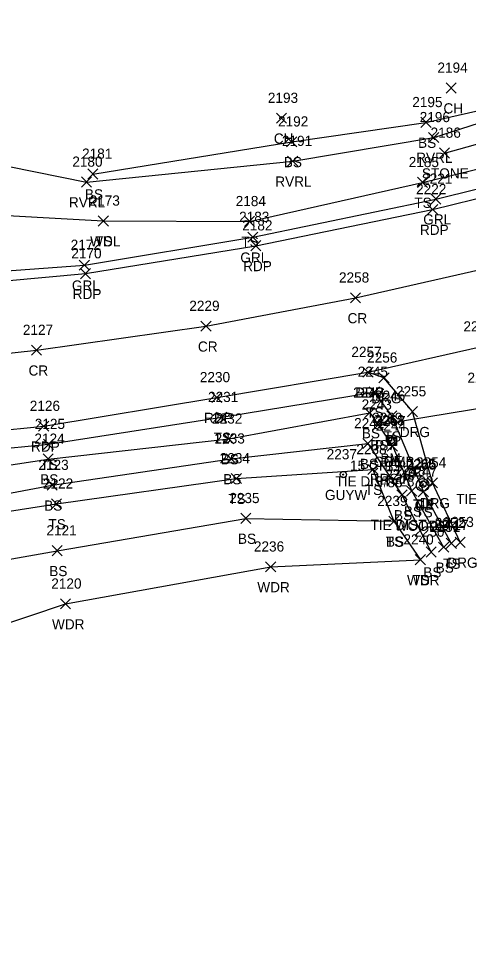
# Model space of a CAD drawing. Extents: x 1699408 to 1700423, y 840176 to 841410.
# Drawn here: x 1699767.4 to 1699855.8, y 840198.9 to 840382.8 of the extents above; entities that cross this region are included whole.
import ezdxf

# ---------------------------------------------------------------- set-up
doc = ezdxf.new("R2010")
doc.units = 0
for name, color, linetype in [('C_A', 7, 'Continuous'), ('C_C', 7, 'Continuous'), ('C_I', 7, 'Continuous'), ('CBP', 7, 'Continuous'), ('CPBM', 7, 'Continuous'), ('D_A', 7, 'Continuous'), ('D_I', 7, 'Continuous'), ('D_TIC', 7, 'Continuous'), ('DCP', 7, 'Continuous'), ('L_A', 7, 'Continuous'), ('L_C', 7, 'Continuous'), ('L_I', 7, 'Continuous'), ('L_TIC', 7, 'Continuous'), ('LASF', 7, 'Continuous'), ('LAWA', 7, 'Continuous'), ('LAWE', 7, 'Continuous'), ('LELB', 7, 'Continuous'), ('P_A', 7, 'Continuous'), ('P_I', 7, 'Continuous'), ('P_TIC', 7, 'Continuous'), ('PET', 7, 'Continuous'), ('PRC', 7, 'Continuous'), ('R_A', 7, 'Continuous'), ('R_C', 7, 'Continuous'), ('R_I', 7, 'Continuous'), ('R_TIC', 7, 'Continuous'), ('RDG', 7, 'Continuous'), ('RGP', 7, 'Continuous'), ('RGR', 7, 'Continuous'), ('U_A', 7, 'Continuous'), ('U_C', 7, 'Continuous'), ('U_I', 7, 'Continuous'), ('UP', 7, 'Continuous'), ('UPGW', 7, 'Continuous')]:
    doc.layers.add(name, color=color, linetype=linetype)

msp = doc.modelspace()

# ---------------------------------------------------------------- linework, layer by layer
at = {"layer": 'CBP'}
for centre, radius in [((1699840.65, 840299.96), 0.625), ((1699840.65, 840299.96), 0.0833), ((1699846.89, 840291.41), 0.625), ((1699846.89, 840291.41), 0.0833)]:
    msp.add_circle(centre, radius, dxfattribs=at)
at = {"layer": 'CPBM'}
for p, q in [((1699839.71, 840299.93), (1699839.71, 840300.94)), ((1699839.71, 840300.94), (1699840.71, 840300.94)), ((1699840.71, 840299.93), (1699839.71, 840299.93)), ((1699840.22, 840300.44), (1699840.22, 840300.44)), ((1699840.22, 840300.44), (1699840.22, 840300.44)), ((1699840.71, 840300.94), (1699840.71, 840299.93))]:
    msp.add_line(p, q, dxfattribs=at)
at = {"layer": 'D_TIC'}
for points in [[(1699837.09, 840302.05), (1699839.09, 840304.05)], [(1699839.09, 840302.05), (1699837.09, 840304.05)]]:
    msp.add_lwpolyline(points, dxfattribs=at)
at = {"layer": 'DCP'}
msp.add_lwpolyline([(1699838.09, 840303.05), (1699866.03, 840307.66)], dxfattribs=at)
at = {"layer": 'L_TIC'}
for points in [[(1699851.44, 840368.2), (1699853.44, 840370.2)], [(1699853.44, 840368.2), (1699851.44, 840370.2)], [(1699818.1, 840362.28), (1699820.1, 840364.28)], [(1699820.1, 840362.28), (1699818.1, 840364.28)], [(1699846.49, 840361.44), (1699848.49, 840363.44)], [(1699848.49, 840361.44), (1699846.49, 840363.44)], [(1699848, 840358.49), (1699850, 840360.49)], [(1699850, 840358.49), (1699848, 840360.49)], [(1699820.1, 840357.64), (1699822.1, 840359.64)], [(1699822.1, 840357.64), (1699820.1, 840359.64)], [(1699850.14, 840355.43), (1699852.14, 840357.43)], [(1699852.14, 840355.43), (1699850.14, 840357.43)], [(1699820.29, 840353.82), (1699822.29, 840355.82)], [(1699822.29, 840353.82), (1699820.29, 840355.82)], [(1699781.01, 840351.31), (1699783.01, 840353.31)], [(1699783.01, 840351.31), (1699781.01, 840353.31)], [(1699779.74, 840349.74), (1699781.74, 840351.74)], [(1699781.74, 840349.74), (1699779.74, 840351.74)], [(1699845.79, 840349.66), (1699847.79, 840351.66)], [(1699847.79, 840349.66), (1699845.79, 840351.66)], [(1699783.06, 840342.1), (1699785.06, 840344.1)], [(1699785.06, 840342.1), (1699783.06, 840344.1)], [(1699783.06, 840342.1), (1699785.06, 840344.1)], [(1699785.06, 840342.1), (1699783.06, 840344.1)], [(1699811.78, 840342), (1699813.78, 840344)], [(1699813.78, 840342), (1699811.78, 840344)], [(1699836.32, 840308.49), (1699838.32, 840310.49)], [(1699838.32, 840308.49), (1699836.32, 840310.49)], [(1699806.33, 840303.54), (1699808.33, 840305.54)], [(1699808.33, 840303.54), (1699806.33, 840305.54)], [(1699835.43, 840304.42), (1699837.43, 840306.42)], [(1699837.43, 840304.42), (1699835.43, 840306.42)], [(1699839.77, 840303.78), (1699841.77, 840305.78)], [(1699841.77, 840303.78), (1699839.77, 840305.78)], [(1699837.09, 840302.05), (1699839.09, 840304.05)], [(1699839.09, 840302.05), (1699837.09, 840304.05)], [(1699772.28, 840298.24), (1699774.28, 840300.24)], [(1699774.28, 840298.24), (1699772.28, 840300.24)], [(1699807.7, 840299.3), (1699809.7, 840301.3)], [(1699809.7, 840299.3), (1699807.7, 840301.3)], [(1699835.05, 840298.39), (1699837.05, 840300.39)], [(1699837.05, 840298.39), (1699835.05, 840300.39)], [(1699839.88, 840297.91), (1699841.88, 840299.91)], [(1699841.88, 840297.91), (1699839.88, 840299.91)], [(1699772.21, 840295.35), (1699774.21, 840297.35)], [(1699774.21, 840295.35), (1699772.21, 840297.35)], [(1699808.19, 840295.39), (1699810.19, 840297.39)], [(1699810.19, 840295.39), (1699808.19, 840297.39)], [(1699836.06, 840293.28), (1699838.06, 840295.28)], [(1699838.06, 840293.28), (1699836.06, 840295.28)], [(1699809.2, 840291.51), (1699811.2, 840293.51)], [(1699811.2, 840291.51), (1699809.2, 840293.51)], [(1699772.99, 840290.21), (1699774.99, 840292.21)], [(1699774.99, 840290.21), (1699772.99, 840292.21)], [(1699843.69, 840289.05), (1699845.69, 840291.05)], [(1699845.69, 840289.05), (1699843.69, 840291.05)], [(1699845.98, 840288.91), (1699847.98, 840290.91)], [(1699847.98, 840288.91), (1699845.98, 840290.91)], [(1699841.76, 840288.31), (1699843.76, 840290.31)], [(1699843.76, 840288.31), (1699841.76, 840290.31)], [(1699773.87, 840286.54), (1699775.87, 840288.54)], [(1699775.87, 840286.54), (1699773.87, 840288.54)], [(1699811.08, 840283.69), (1699813.08, 840285.69)], [(1699813.08, 840283.69), (1699811.08, 840285.69)], [(1699840.18, 840283.12), (1699842.18, 840285.12)], [(1699842.18, 840283.12), (1699840.18, 840285.12)], [(1699840.18, 840283.12), (1699842.18, 840285.12)], [(1699842.18, 840283.12), (1699840.18, 840285.12)], [(1699849.95, 840278.03), (1699851.95, 840280.03)], [(1699851.95, 840278.03), (1699849.95, 840280.03)], [(1699851.46, 840278.79), (1699853.46, 840280.79)], [(1699853.46, 840278.79), (1699851.46, 840280.79)], [(1699773.99, 840277.35), (1699775.99, 840279.35)], [(1699775.99, 840277.35), (1699773.99, 840279.35)], [(1699847.51, 840277.09), (1699849.51, 840279.09)], [(1699849.51, 840277.09), (1699847.51, 840279.09)], [(1699815.97, 840274.18), (1699817.97, 840276.18)], [(1699817.97, 840274.18), (1699815.97, 840276.18)], [(1699845.39, 840275.57), (1699847.39, 840277.57)], [(1699847.39, 840275.57), (1699845.39, 840277.57)], [(1699845.39, 840275.57), (1699847.39, 840277.57)], [(1699847.39, 840275.57), (1699845.39, 840277.57)], [(1699775.61, 840266.9), (1699777.61, 840268.9)], [(1699777.61, 840266.9), (1699775.61, 840268.9)]]:
    msp.add_lwpolyline(points, dxfattribs=at)
at = {"layer": 'LASF'}
msp.add_lwpolyline([(1699851.14, 840356.43), (1699867.77, 840361.02), (1699888.01, 840366.67), (1699907.74, 840370.19), (1699925.07, 840381), (1699922.64, 840389.58)], dxfattribs=at)
at = {"layer": 'LAWA'}
for points in [[(1699556.13, 840340.53), (1699588.5, 840337.27), (1699620.6, 840336.18), (1699665.74, 840339.57), (1699700.67, 840345.7), (1699729.87, 840346.11), (1699784.06, 840343.1)], [(1699633.39, 840226.83), (1699656.37, 840240.6), (1699684.65, 840244.27), (1699713.47, 840248.67), (1699728.44, 840253.97), (1699747.5, 840258.18), (1699776.61, 840267.9), (1699816.97, 840275.18), (1699846.39, 840276.57)]]:
    msp.add_lwpolyline(points, dxfattribs=at)
at = {"layer": 'LAWE'}
msp.add_lwpolyline([(1699729.36, 840377.19), (1699755.12, 840355.85), (1699780.74, 840350.74), (1699821.29, 840354.82), (1699849, 840359.49), (1699872.08, 840366.87), (1699889.41, 840374.37), (1699901.94, 840377.56)], dxfattribs=at)
at = {"layer": 'LELB'}
for points in [[(1699782.01, 840352.31), (1699821.1, 840358.64), (1699847.49, 840362.44), (1699872, 840367.97), (1699887.26, 840376.59), (1699902.6, 840378.37), (1699905.68, 840380.36), (1699909.75, 840383.88), (1699917.88, 840388.51), (1699929.29, 840395.23), (1699957.95, 840421.92), (1699988.44, 840440.99)], [(1699784.06, 840343.1), (1699812.78, 840343), (1699846.79, 840350.66), (1699873.28, 840357.14), (1699911.79, 840368.31), (1699928.14, 840374.26), (1699963.63, 840390.16), (1699976.97, 840400.87)], [(1699449.32, 840203.24), (1699477.66, 840221.47), (1699508.6, 840240.03), (1699538.28, 840254.01), (1699565.8, 840264.7), (1699593.44, 840273.59), (1699619.93, 840280.17), (1699647.78, 840284.89), (1699680.49, 840289.58), (1699709.99, 840292.62), (1699741.26, 840296.11), (1699773.28, 840299.24), (1699807.33, 840304.54), (1699837.32, 840309.49), (1699840.77, 840304.78), (1699846.98, 840289.91), (1699852.46, 840279.79)], [(1699450.68, 840200.86), (1699478.43, 840220.04), (1699510.71, 840237.45), (1699539.18, 840250.98), (1699567.45, 840262.15), (1699594.13, 840270.62), (1699621.67, 840276.44), (1699649, 840280.25), (1699681.32, 840285.34), (1699711.01, 840288.64), (1699741.71, 840291.52), (1699773.21, 840296.35), (1699808.7, 840300.3), (1699836.43, 840305.42), (1699838.09, 840303.05), (1699840.88, 840298.91), (1699844.69, 840290.05), (1699850.95, 840279.03)], [(1699452.04, 840198.91), (1699479.59, 840217.72), (1699512.19, 840235.39), (1699539.84, 840249.47), (1699568.3, 840260.42), (1699595.02, 840268.85), (1699623.34, 840272.03), (1699650.02, 840274.02), (1699683.39, 840277.43), (1699712.27, 840281.78), (1699743, 840285.37), (1699773.99, 840291.21), (1699809.19, 840296.39), (1699836.05, 840299.39), (1699842.76, 840289.31), (1699848.51, 840278.09)], [(1699623.59, 840268.72), (1699650.55, 840270.46), (1699684.26, 840273.9), (1699713.02, 840278.92), (1699743.28, 840282.61), (1699774.87, 840287.54), (1699810.2, 840292.51), (1699837.06, 840294.28), (1699841.18, 840284.12), (1699846.39, 840276.57)], [(1699679.94, 840264.57), (1699712.9, 840268.9), (1699744.46, 840272.92), (1699774.99, 840278.35), (1699812.08, 840284.69), (1699841.18, 840284.12)]]:
    msp.add_lwpolyline(points, dxfattribs=at)
at = {"layer": 'P_TIC'}
for points in [[(1699847.8, 840344.35), (1699849.8, 840346.35)], [(1699849.8, 840344.35), (1699847.8, 840346.35)], [(1699813.05, 840337.23), (1699815.05, 840339.23)], [(1699815.05, 840337.23), (1699813.05, 840339.23)], [(1699779.55, 840331.75), (1699781.55, 840333.75)], [(1699781.55, 840331.75), (1699779.55, 840333.75)], [(1699832.64, 840327), (1699834.64, 840329)], [(1699834.64, 840327), (1699832.64, 840329)], [(1699803.23, 840321.43), (1699805.23, 840323.43)], [(1699805.23, 840321.43), (1699803.23, 840323.43)], [(1699769.93, 840316.73), (1699771.93, 840318.73)], [(1699771.93, 840316.73), (1699769.93, 840318.73)], [(1699835.08, 840312.39), (1699837.08, 840314.39)], [(1699837.08, 840312.39), (1699835.08, 840314.39)], [(1699805.37, 840307.43), (1699807.37, 840309.43)], [(1699807.37, 840307.43), (1699805.37, 840309.43)], [(1699771.35, 840301.79), (1699773.35, 840303.79)], [(1699773.35, 840301.79), (1699771.35, 840303.79)]]:
    msp.add_lwpolyline(points, dxfattribs=at)
at = {"layer": 'PET'}
for points in [[(1699430.72, 840228.22), (1699466.92, 840252.65), (1699493.58, 840268.87), (1699501.63, 840273.58), (1699505.33, 840277.49), (1699516.37, 840283.58), (1699542.26, 840294.23), (1699569.87, 840304.55), (1699598.29, 840312.45), (1699620.64, 840316.32), (1699670.9, 840322.33), (1699702.16, 840325.07), (1699741.15, 840329.16), (1699780.55, 840332.75), (1699814.05, 840338.23), (1699848.8, 840345.35), (1699873.3, 840351.35), (1699914.22, 840362.32), (1699930.57, 840367.02), (1699959.45, 840375.82), (1699990.91, 840385.72), (1700021.62, 840396.71), (1700043.81, 840403.93)], [(1699447.11, 840206.16), (1699475.63, 840224.65), (1699506.94, 840242.78), (1699536.09, 840256.08), (1699564.51, 840267.73), (1699591.88, 840277.12), (1699619.21, 840283.47), (1699647.22, 840288.99), (1699679.73, 840293.47), (1699710.33, 840296.95), (1699740.62, 840299.68), (1699772.35, 840302.79), (1699806.37, 840308.43), (1699836.08, 840313.39), (1699858.12, 840318.39), (1699877.08, 840323.18), (1699900.35, 840329.36), (1699935.97, 840340.61), (1699968.58, 840349.28), (1700000.7, 840359.42), (1700031.35, 840369.03)]]:
    msp.add_lwpolyline(points, dxfattribs=at)
at = {"layer": 'PRC'}
msp.add_lwpolyline([(1699438.11, 840217.33), (1699474.74, 840241.27), (1699500.34, 840255.97), (1699530.26, 840270.89), (1699558.33, 840282.59), (1699589.24, 840292.75), (1699616.86, 840299.45), (1699644.68, 840304.26), (1699678.81, 840308.53), (1699708.26, 840311.1), (1699739.11, 840314.27), (1699770.93, 840317.73), (1699804.23, 840322.43), (1699833.64, 840328), (1699873.5, 840337.02), (1699896.6, 840342.97), (1699933.32, 840353.07), (1699963.1, 840362.17), (1699996.81, 840372.51), (1700026.94, 840382.38)], dxfattribs=at)
at = {"layer": 'R_TIC'}
for points in [[(1699848.41, 840346.4), (1699850.41, 840348.4)], [(1699850.41, 840346.4), (1699848.41, 840348.4)], [(1699812.44, 840338.9), (1699814.44, 840340.9)], [(1699814.44, 840338.9), (1699812.44, 840340.9)], [(1699779.34, 840333.41), (1699781.34, 840335.41)], [(1699781.34, 840333.41), (1699779.34, 840335.41)], [(1699835.08, 840312.39), (1699837.08, 840314.39)], [(1699837.08, 840312.39), (1699835.08, 840314.39)], [(1699838.23, 840311.28), (1699840.23, 840313.28)], [(1699840.23, 840311.28), (1699838.23, 840313.28)], [(1699843.84, 840304.65), (1699845.84, 840306.65)], [(1699845.84, 840304.65), (1699843.84, 840306.65)], [(1699847.78, 840290.68), (1699849.78, 840292.68)], [(1699849.78, 840290.68), (1699847.78, 840292.68)], [(1699853.2, 840278.99), (1699855.2, 840280.99)], [(1699855.2, 840278.99), (1699853.2, 840280.99)]]:
    msp.add_lwpolyline(points, dxfattribs=at)
at = {"layer": 'RDG'}
msp.add_lwpolyline([(1699854.2, 840279.99), (1699848.78, 840291.68), (1699844.84, 840305.65), (1699839.23, 840312.28), (1699836.08, 840313.39)], dxfattribs=at)
at = {"layer": 'RGP'}
msp.add_line((1699846.83, 840291.25), (1699846.83, 840291.25), dxfattribs=at)
for radius in [1.25, 0.0833]:
    msp.add_circle((1699846.83, 840291.25), radius, dxfattribs=at)
at = {"layer": 'RGR'}
msp.add_lwpolyline([(1699728.48, 840335.43), (1699752.54, 840332.39), (1699780.34, 840334.41), (1699813.44, 840339.9), (1699849.41, 840347.4), (1699873.97, 840353.47), (1699916.95, 840364.91), (1699929.95, 840368.59), (1699959.73, 840377.35), (1699990.11, 840387.92), (1700008.42, 840397.8)], dxfattribs=at)
at = {"layer": 'UP'}
for p, q in [((1699840, 840298.97), (1699840, 840300.64)), ((1699840, 840300.64), (1699841.67, 840300.64)), ((1699841.09, 840301.47), (1699840.84, 840300.64)), ((1699840.84, 840299.8), (1699840.84, 840299.8)), ((1699841.67, 840300.64), (1699841.67, 840298.97)), ((1699841.67, 840298.97), (1699840, 840298.97)), ((1699840.59, 840298.14), (1699840.84, 840298.97))]:
    msp.add_line(p, q, dxfattribs=at)
msp.add_circle((1699840.84, 840299.8), 0.833, dxfattribs=at)
at = {"layer": 'UPGW'}
for radius in [0.625, 0.0833]:
    msp.add_circle((1699831.23, 840293.29), radius, dxfattribs=at)

# ---------------------------------------------------------------- texts
at = {"layer": 'C_A'}
for s, p in [('BM', (1699838.53, 840295.44)), ('TIE', (1699838.73, 840294.96)), ('TIE', (1699844.97, 840286.41))]:
    msp.add_text(s, height=2, dxfattribs=at).set_placement(p)
at = {"layer": 'C_C'}
for s, p in [('TIE DIST=28.20', (1699829.69, 840290.96)), ('RRSIP', (1699836.43, 840291.44)), ('TIE DIST=18.42', (1699853.43, 840287.5)), ('TIE DIST=29.17', (1699836.6, 840282.41))]:
    msp.add_text(s, height=2, dxfattribs=at).set_placement(p)
at = {"layer": 'C_I'}
for s, p in [('2269', (1699836.9, 840303.44)), ('2268', (1699837.34, 840302.96)), ('2265', (1699843.59, 840294.41))]:
    msp.add_text(s, height=2, dxfattribs=at).set_placement(p)
at = {"layer": 'D_A'}
msp.add_text('P', height=2, dxfattribs=at).set_placement((1699837.47, 840298.05))
at = {"layer": 'D_I'}
msp.add_text('2243', height=2, dxfattribs=at).set_placement((1699834.83, 840306.05))
at = {"layer": 'L_A'}
for s, p in [('CH', (1699850.92, 840364.2)), ('CH', (1699817.58, 840358.28)), ('BS', (1699845.93, 840357.44)), ('BS', (1699819.54, 840353.64)), ('RVRL', (1699845.56, 840354.49)), ('STONE', (1699846.68, 840351.43)), ('RVRL', (1699817.86, 840349.82)), ('BS', (1699780.45, 840347.31)), ('RVRL', (1699777.3, 840345.74)), ('TS', (1699845.2, 840345.66)), ('WDL', (1699781.47, 840338.1)), ('TS', (1699782.47, 840338.1)), ('TS', (1699811.19, 840338)), ('TS', (1699835.73, 840304.49)), ('TS', (1699805.74, 840299.54)), ('BS', (1699834.87, 840300.42)), ('TS', (1699839.18, 840299.78)), ('BS', (1699836.53, 840298.05)), ('TS', (1699771.69, 840294.24)), ('BS', (1699807.14, 840295.3)), ('BS', (1699834.49, 840294.39)), ('BS', (1699839.32, 840293.91)), ('BS', (1699771.65, 840291.35)), ('BS', (1699807.63, 840291.39)), ('TS', (1699835.47, 840289.28)), ('TS', (1699808.61, 840287.51)), ('BS', (1699772.43, 840286.21)), ('BS', (1699843.14, 840285.05)), ('TS', (1699845.39, 840284.91)), ('BS', (1699841.2, 840284.31)), ('TS', (1699773.28, 840282.54)), ('BS', (1699810.52, 840279.69)), ('TS', (1699839.59, 840279.12)), ('BS', (1699839.62, 840279.12)), ('BS', (1699849.39, 840274.03)), ('TS', (1699850.86, 840274.79)), ('BS', (1699773.43, 840273.35)), ('BS', (1699846.96, 840273.09)), ('WDR', (1699814.33, 840270.18)), ('WDR', (1699843.76, 840271.57)), ('TS', (1699844.8, 840271.57)), ('WDR', (1699773.97, 840262.9))]:
    msp.add_text(s, height=2, dxfattribs=at).set_placement(p)
at = {"layer": 'L_C'}
msp.add_text('15 CPEP', height=2, dxfattribs=at).set_placement((1699832.56, 840294.05))
at = {"layer": 'L_I'}
for s, p in [('2194', (1699849.74, 840372.2)), ('2193', (1699816.4, 840366.28)), ('2195', (1699844.79, 840365.44)), ('2196', (1699846.25, 840362.49)), ('2192', (1699818.4, 840361.64)), ('2186', (1699848.39, 840359.43)), ('2191', (1699819.17, 840357.82)), ('2181', (1699779.88, 840355.31)), ('2180', (1699777.96, 840353.74)), ('2185', (1699844.09, 840353.66)), ('2173', (1699781.36, 840346.1)), ('2173', (1699781.36, 840346.1)), ('2184', (1699810.08, 840346)), ('2245', (1699834.06, 840312.49)), ('2231', (1699804.64, 840307.54)), ('2242', (1699833.17, 840308.42)), ('2246', (1699837.46, 840307.78)), ('2243', (1699834.83, 840306.05)), ('2232', (1699805.44, 840303.3)), ('2125', (1699770.58, 840302.24)), ('2241', (1699833.36, 840302.39)), ('2244', (1699837.62, 840301.91)), ('2124', (1699770.51, 840299.35)), ('2233', (1699805.93, 840299.39)), ('2238', (1699833.8, 840297.28)), ('2123', (1699771.3, 840294.21)), ('2234', (1699806.94, 840295.51)), ('2249', (1699839.49, 840292.31)), ('2248', (1699841.43, 840293.05)), ('2247', (1699843.72, 840292.91)), ('2122', (1699772.18, 840290.54)), ('2235', (1699808.82, 840287.69)), ('2239', (1699837.91, 840287.12)), ('2239', (1699837.91, 840287.12)), ('2121', (1699772.87, 840281.35)), ('2251', (1699848.26, 840282.03)), ('2252', (1699849.2, 840282.79)), ('2240', (1699843.05, 840279.57)), ('2240', (1699843.05, 840279.57)), ('2250', (1699845.17, 840281.09)), ('2236', (1699813.66, 840278.18)), ('2120', (1699773.83, 840270.9))]:
    msp.add_text(s, height=2, dxfattribs=at).set_placement(p)
at = {"layer": 'P_A'}
for s, p in [('RDP', (1699846.29, 840340.35)), ('RDP', (1699811.54, 840333.23)), ('RDP', (1699778.04, 840327.75)), ('CR', (1699832.07, 840323)), ('CR', (1699802.66, 840317.43)), ('CR', (1699769.36, 840312.73)), ('RDP', (1699833.57, 840308.39)), ('RDP', (1699803.86, 840303.43)), ('RDP', (1699769.84, 840297.79))]:
    msp.add_text(s, height=2, dxfattribs=at).set_placement(p)
at = {"layer": 'P_I'}
for s, p in [('2222', (1699845.54, 840348.35)), ('2182', (1699811.36, 840341.23)), ('2170', (1699777.77, 840335.75)), ('2258', (1699830.38, 840331)), ('2229', (1699800.96, 840325.43)), ('2127', (1699768.24, 840320.73)), ('2259', (1699854.85, 840321.39)), ('2257', (1699832.82, 840316.39)), ('2230', (1699803.03, 840311.43)), ('2126', (1699769.6, 840305.79))]:
    msp.add_text(s, height=2, dxfattribs=at).set_placement(p)
at = {"layer": 'R_A'}
for s, p in [('GRL', (1699846.95, 840342.4)), ('GRL', (1699810.99, 840334.9)), ('GRL', (1699777.88, 840329.41)), ('DRG', (1699833.57, 840308.39)), ('DRG', (1699836.72, 840307.28)), ('DRG', (1699842.33, 840300.65)), ('DRG', (1699846.26, 840286.68)), ('GP', (1699845.26, 840286.25)), ('DRG', (1699851.69, 840274.99))]:
    msp.add_text(s, height=2, dxfattribs=at).set_placement(p)
at = {"layer": 'R_C'}
msp.add_text('WOODEN', height=2, dxfattribs=at).set_placement((1699841.34, 840282.25))
at = {"layer": 'R_I'}
for s, p in [('2221', (1699846.72, 840350.4)), ('2183', (1699810.75, 840342.9)), ('2172', (1699777.64, 840337.41)), ('2259', (1699854.85, 840321.39)), ('2257', (1699832.82, 840316.39)), ('2256', (1699835.91, 840315.28)), ('2260', (1699855.64, 840311.31)), ('2255', (1699841.58, 840308.65)), ('2266', (1699843.47, 840294.25)), ('2254', (1699845.52, 840294.68)), ('2253', (1699850.94, 840282.99))]:
    msp.add_text(s, height=2, dxfattribs=at).set_placement(p)
at = {"layer": 'U_A'}
for s, p in [('COMB', (1699837.22, 840294.8)), ('GUYW', (1699827.63, 840288.29))]:
    msp.add_text(s, height=2, dxfattribs=at).set_placement(p)
at = {"layer": 'U_C'}
msp.add_text('#86', height=2, dxfattribs=at).set_placement((1699838.42, 840290.8))
at = {"layer": 'U_I'}
for s, p in [('2267', (1699837.53, 840302.8)), ('2237', (1699827.97, 840296.29))]:
    msp.add_text(s, height=2, dxfattribs=at).set_placement(p)

doc.saveas('drawing.dxf')
